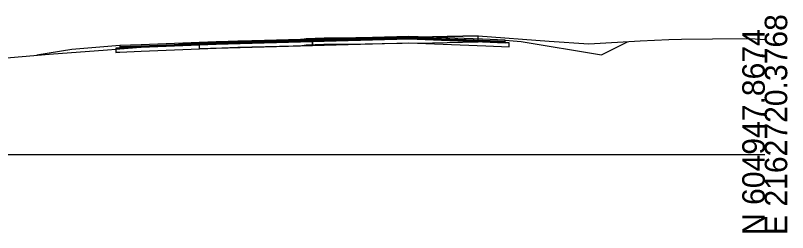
# Model space of a CAD drawing. Extents: x -26 to 1303, y -10 to 12038.
# Drawn here: x 206.6 to 302.8, y 10990.3 to 11017.3 of the extents above; entities that cross this region are included whole.
import ezdxf

# ---------------------------------------------------------------- set-up
doc = ezdxf.new("R2010")
doc.units = 0
for name, color, linetype in [('RD_GPK_XS_Cell', 7, 'Continuous'), ('RD_XS_Base', 7, 'Continuous'), ('RD_XS_ExGround', 7, 'Continuous'), ('RD_XS_ExPaveRet', 7, 'Continuous'), ('RD_XS_Greenside', 7, 'Continuous'), ('RD_XS_Pave', 7, 'Continuous'), ('RD_XS_PaveOvlay_CP', 7, 'Continuous'), ('RD_XS_TieSlope', 7, 'Continuous')]:
    doc.layers.add(name, color=color, linetype=linetype)

msp = doc.modelspace()

# ---------------------------------------------------------------- linework, layer by layer
at = {"layer": 'RD_GPK_XS_Cell'}
msp.add_line((150, 11000), (300, 11000), dxfattribs=at)
at = {"layer": 'RD_XS_Base'}
for p, q in [((243.646, 11014.069), (231.646, 11013.733)), ((243.646, 11014.108), (243.646, 11014.228)), ((243.646, 11014.228), (243.646, 11013.731)), ((246.578, 11014.151), (243.646, 11014.069)), ((243.646, 11014.069), (243.646, 11014.108)), ((243.646, 11014.069), (243.646, 11014.069)), ((243.646, 11014.069), (243.646, 11014.069)), ((243.646, 11013.692), (243.646, 11014.069)), ((255.646, 11014.405), (246.578, 11014.151)), ((246.578, 11013.651), (255.646, 11013.905)), ((264.839, 11014.038), (255.646, 11014.405)), ((255.646, 11013.905), (265.225, 11013.523)), ((267.646, 11013.926), (264.839, 11014.038)), ((268.031, 11013.91), (267.646, 11013.926)), ((268.146, 11013.906), (268.031, 11013.91)), ((268.146, 11013.522), (268.146, 11013.906)), ((219.279, 11013.238), (219.146, 11013.232)), ((219.146, 11013.232), (219.146, 11012.866)), ((219.146, 11012.866), (219.146, 11012.732)), ((219.646, 11013.252), (219.279, 11013.238)), ((222.297, 11013.359), (219.646, 11013.252)), ((219.646, 11012.752), (222.297, 11012.859)), ((231.646, 11013.733), (222.297, 11013.359)), ((222.297, 11012.859), (231.646, 11013.233)), ((231.646, 11013.233), (243.646, 11013.569)), ((243.646, 11013.731), (243.646, 11013.569)), ((243.646, 11013.569), (243.646, 11013.692)), ((243.646, 11013.569), (246.578, 11013.651)), ((265.225, 11013.523), (268.146, 11013.406)), ((268.146, 11013.406), (268.146, 11013.522)), ((219.146, 11012.732), (219.279, 11012.738)), ((219.279, 11012.738), (219.646, 11012.752))]:
    msp.add_line(p, q, dxfattribs=at)
at = {"layer": 'RD_XS_ExGround'}
msp.add_lwpolyline([(204.079, 11011.914), (210.83, 11012.5), (218.117, 11013.062), (229.521, 11013.941), (234.356, 11014.124), (242.325, 11014.316), (242.954, 11014.432), (244.361, 11014.458), (244.811, 11014.471), (244.93, 11014.453), (245.113, 11014.486), (246.726, 11014.484), (247.809, 11014.499), (250.197, 11014.538), (254.655, 11014.619), (258.598, 11014.681), (264.295, 11014.77), (273.149, 11014.132), (278.061, 11013.798), (284.459, 11014.174), (288.026, 11014.344), (289.619, 11014.371), (293.487, 11014.406), (298.224, 11014.453), (300, 11014.347)], dxfattribs=at)
at = {"layer": 'RD_XS_ExPaveRet'}
msp.add_lwpolyline([(260.421, 11014.71), (258.598, 11014.681), (254.838, 11014.622), (254.655, 11014.619), (254.446, 11014.616), (250.197, 11014.538), (249.04, 11014.519), (247.809, 11014.499), (247.256, 11014.491), (246.726, 11014.484), (245.335, 11014.485), (245.113, 11014.486), (244.956, 11014.458), (244.93, 11014.453), (244.827, 11014.469), (244.811, 11014.471), (244.749, 11014.469), (244.361, 11014.458), (243.985, 11014.451), (242.954, 11014.432), (242.87, 11014.417), (242.325, 11014.316), (241.245, 11014.29), (234.356, 11014.124), (232.359, 11014.048), (229.521, 11013.941), (229.521, 11013.375), (229.521, 11013.191), (232.359, 11013.298), (234.356, 11013.374), (241.245, 11013.54), (242.325, 11013.566), (242.87, 11013.667), (242.954, 11013.682), (243.985, 11013.701), (244.361, 11013.708), (244.749, 11013.719), (244.811, 11013.721), (244.827, 11013.719), (244.93, 11013.703), (244.956, 11013.708), (245.113, 11013.736), (245.335, 11013.735), (246.726, 11013.734), (247.256, 11013.741), (247.809, 11013.749), (249.04, 11013.769), (250.197, 11013.788), (254.446, 11013.866), (254.655, 11013.869), (254.838, 11013.872), (258.598, 11013.931), (260.421, 11013.96), (264.295, 11014.02), (264.295, 11014.171), (264.295, 11014.77), (260.421, 11014.71)], dxfattribs=at)
msp.add_lwpolyline([(260.421, 11014.71), (258.598, 11014.681), (254.838, 11014.622), (254.655, 11014.619), (254.446, 11014.616), (250.197, 11014.538), (249.04, 11014.519), (247.809, 11014.499), (247.256, 11014.491), (246.726, 11014.484), (245.335, 11014.485), (245.113, 11014.486), (244.956, 11014.458), (244.93, 11014.453), (244.827, 11014.469), (244.811, 11014.471), (244.749, 11014.469), (244.361, 11014.458), (243.985, 11014.451), (242.954, 11014.432), (242.87, 11014.417), (242.325, 11014.316), (241.245, 11014.29), (234.356, 11014.124), (232.359, 11014.048), (229.521, 11013.941), (229.521, 11013.375), (229.521, 11013.191), (232.359, 11013.298), (234.356, 11013.374), (241.245, 11013.54), (242.325, 11013.566), (242.87, 11013.667), (242.954, 11013.682), (243.985, 11013.701), (244.361, 11013.708), (244.749, 11013.719), (244.811, 11013.721), (244.827, 11013.719), (244.93, 11013.703), (244.956, 11013.708), (245.113, 11013.736), (245.335, 11013.735), (246.726, 11013.734), (247.256, 11013.741), (247.809, 11013.749), (249.04, 11013.769), (250.197, 11013.788), (254.446, 11013.866), (254.655, 11013.869), (254.838, 11013.872), (258.598, 11013.931), (260.421, 11013.96), (264.295, 11014.02), (264.295, 11014.171), (264.295, 11014.77), (260.421, 11014.71)], dxfattribs=at)
at = {"layer": 'RD_XS_Greenside'}
for p, q in [((269.646, 11014.084), (279.647, 11012.417)), ((279.647, 11012.417), (282.883, 11014.035)), ((213.646, 11013.09), (209.319, 11012.369))]:
    msp.add_line(p, q, dxfattribs=at)
at = {"layer": 'RD_XS_Pave'}
for p, q in [((255.646, 11014.723), (246.578, 11014.469)), ((264.839, 11014.356), (255.646, 11014.723)), ((231.646, 11014.051), (222.297, 11013.677)), ((231.646, 11013.892), (222.297, 11013.518)), ((222.297, 11013.518), (231.646, 11013.892)), ((243.646, 11014.387), (231.646, 11014.051)), ((243.646, 11014.228), (231.646, 11013.892)), ((231.646, 11013.892), (243.646, 11014.228)), ((231.646, 11013.733), (243.646, 11014.069)), ((246.578, 11014.469), (243.646, 11014.387)), ((246.578, 11014.31), (243.646, 11014.228)), ((243.646, 11014.228), (246.578, 11014.31)), ((243.646, 11014.108), (243.646, 11014.228)), ((243.646, 11014.228), (243.646, 11014.228)), ((243.646, 11014.228), (243.646, 11014.228)), ((243.646, 11014.228), (243.646, 11014.108)), ((243.646, 11014.069), (246.578, 11014.151)), ((243.646, 11014.069), (243.646, 11014.108)), ((243.646, 11014.108), (243.646, 11014.069)), ((243.646, 11014.069), (243.646, 11014.069)), ((243.646, 11014.069), (243.646, 11014.069)), ((255.646, 11014.564), (246.578, 11014.31)), ((246.578, 11014.31), (255.646, 11014.564)), ((246.578, 11014.151), (255.646, 11014.405)), ((264.839, 11014.197), (255.646, 11014.564)), ((255.646, 11014.564), (264.839, 11014.197)), ((255.646, 11014.405), (264.839, 11014.038)), ((267.646, 11014.244), (264.839, 11014.356)), ((267.646, 11014.085), (264.839, 11014.197)), ((264.839, 11014.197), (267.646, 11014.085)), ((264.839, 11014.038), (267.646, 11013.926)), ((267.646, 11014.122), (267.646, 11014.244)), ((267.646, 11014.085), (267.646, 11014.122)), ((267.646, 11013.963), (267.646, 11014.085)), ((267.646, 11013.926), (267.646, 11013.963)), ((222.297, 11013.677), (219.646, 11013.57)), ((219.646, 11013.57), (219.646, 11013.454)), ((222.297, 11013.518), (219.646, 11013.411)), ((219.646, 11013.411), (222.297, 11013.518)), ((219.646, 11013.454), (219.646, 11013.411)), ((219.646, 11013.411), (219.646, 11013.295)), ((219.646, 11013.252), (222.297, 11013.359)), ((219.646, 11013.295), (219.646, 11013.252)), ((222.297, 11013.359), (231.646, 11013.733))]:
    msp.add_line(p, q, dxfattribs=at)
at = {"layer": 'RD_XS_PaveOvlay_CP'}
for p, q in [((255.646, 11014.723), (246.578, 11014.469)), ((264.839, 11014.356), (255.646, 11014.723)), ((231.646, 11014.051), (222.297, 11013.677)), ((243.646, 11014.387), (231.646, 11014.051)), ((246.578, 11014.469), (243.646, 11014.387)), ((267.646, 11014.244), (264.839, 11014.356)), ((222.297, 11013.677), (219.646, 11013.57))]:
    msp.add_line(p, q, dxfattribs=at)
at = {"layer": 'RD_XS_TieSlope'}
for p, q in [((267.646, 11014.244), (269.646, 11014.084)), ((219.646, 11013.57), (213.646, 11013.09))]:
    msp.add_line(p, q, dxfattribs=at)

# ---------------------------------------------------------------- texts
at = {"layer": 'RD_GPK_XS_Cell'}
for s, p in [('E 2162720.3768', (302.8, 10990)), ('N 604947.8674', (300, 10990))]:
    msp.add_text(s, height=2.8, rotation=90, dxfattribs=at).set_placement(p)

doc.saveas('drawing.dxf')
